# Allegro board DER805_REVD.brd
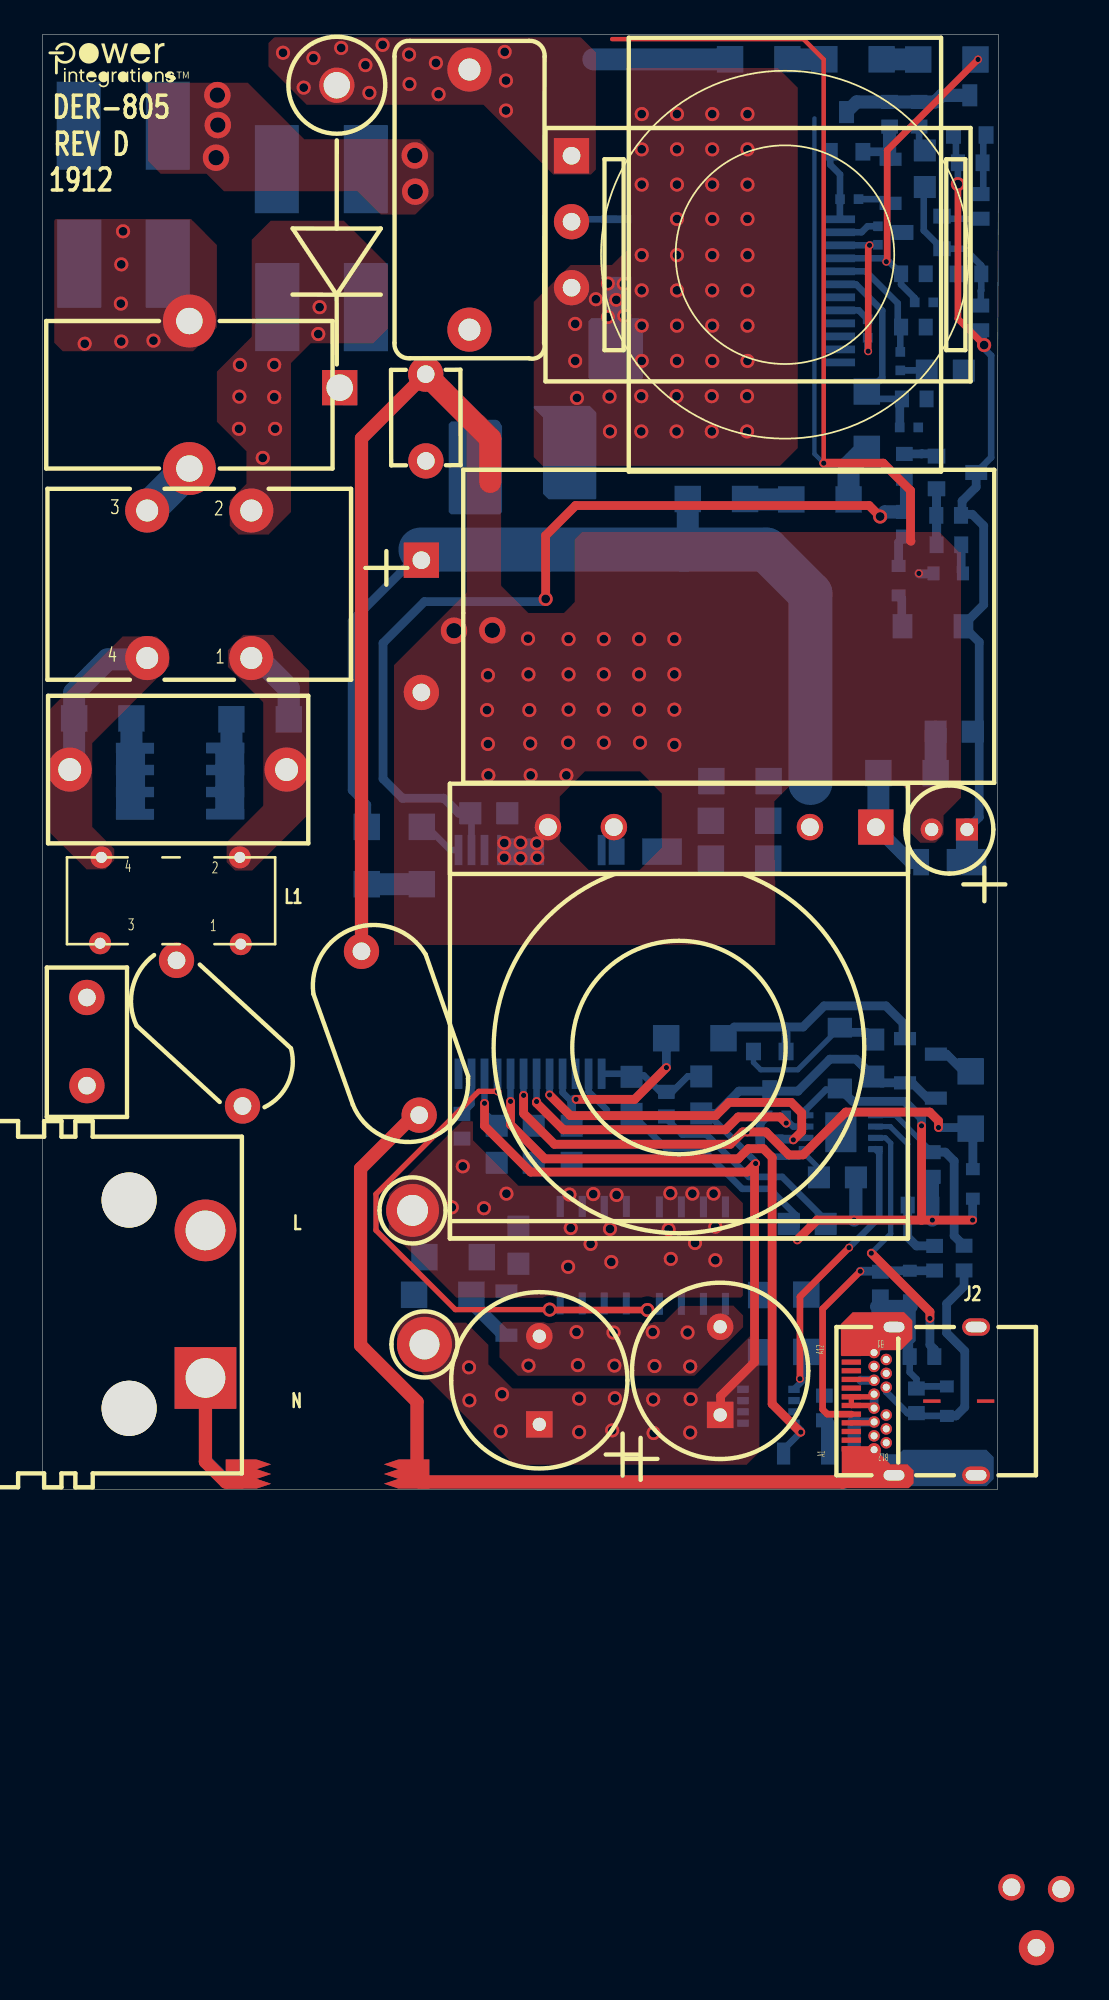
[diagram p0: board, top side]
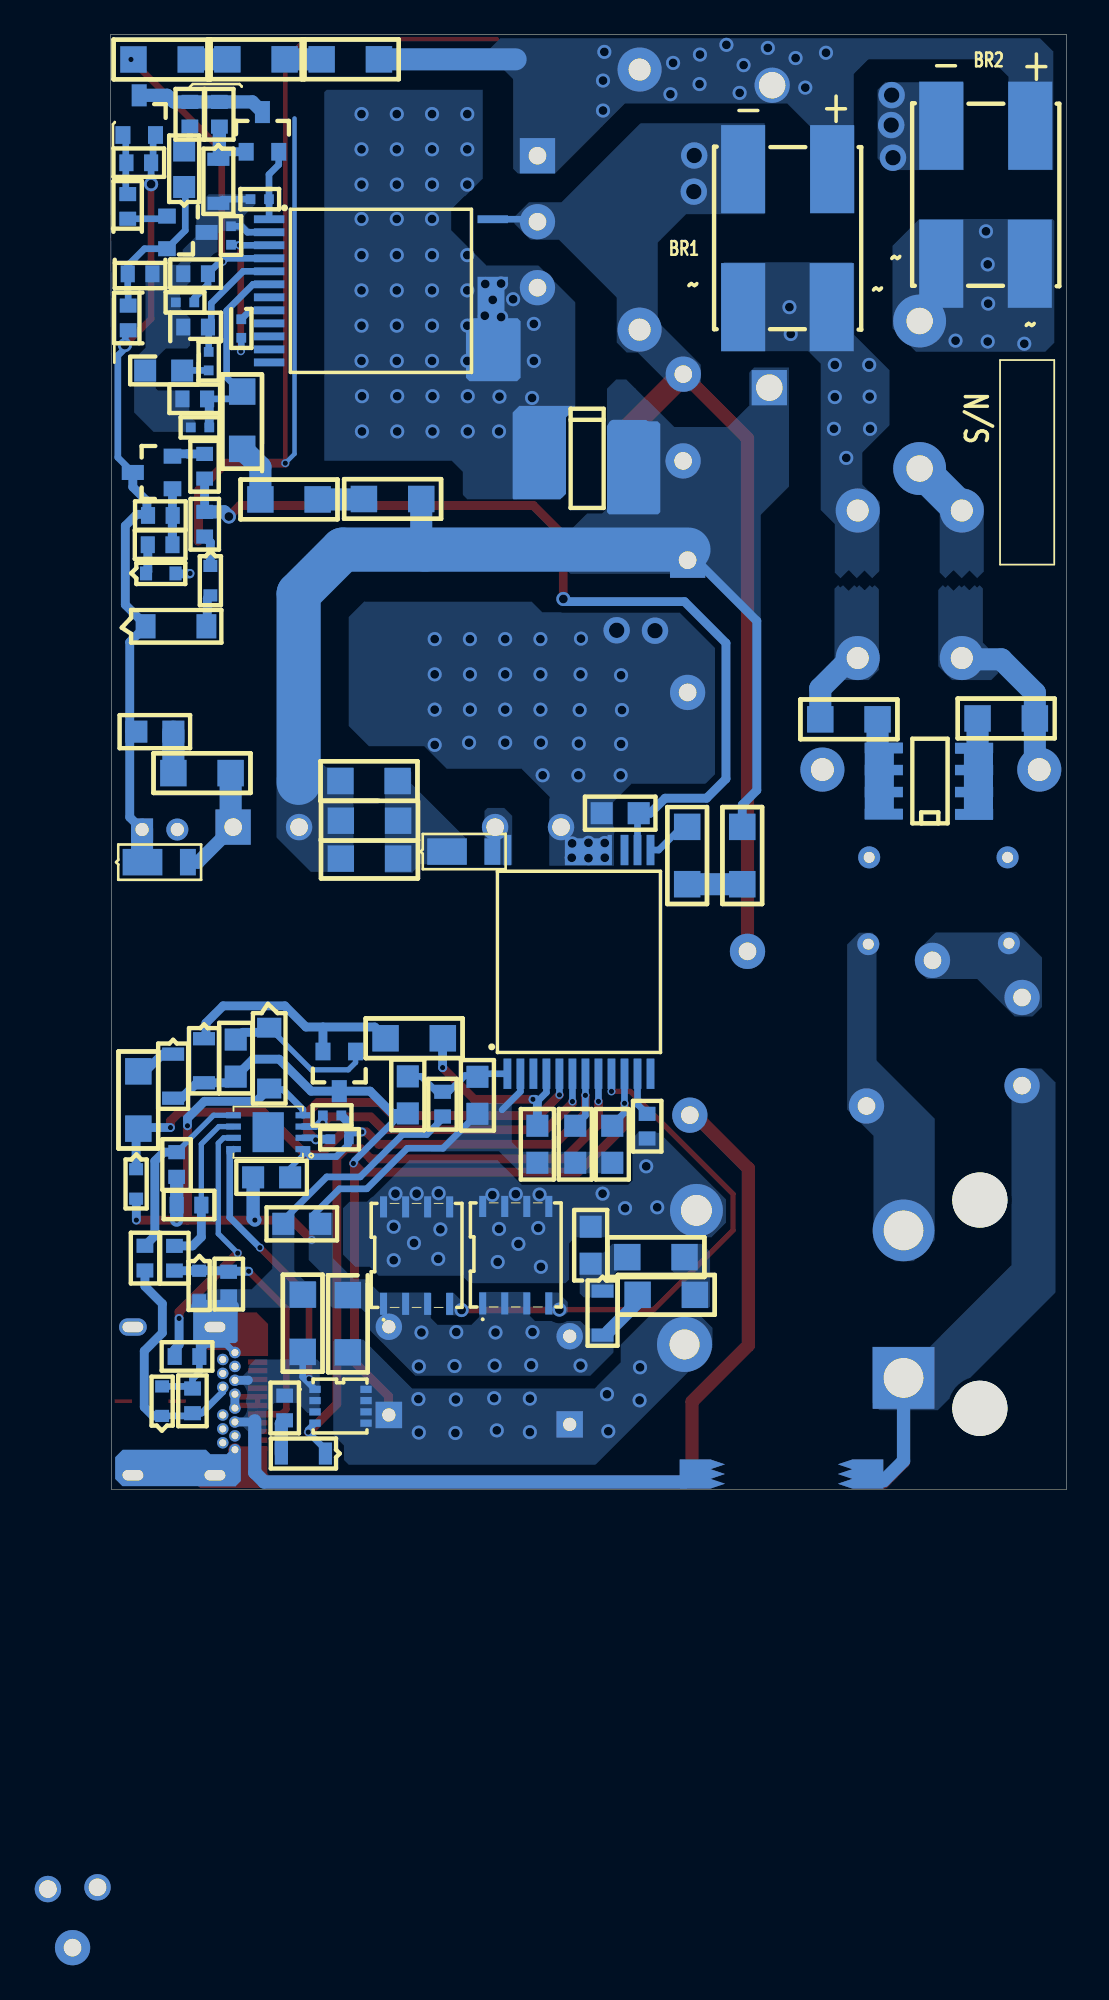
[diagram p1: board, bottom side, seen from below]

Outline 55.12 x 83.82 mm; copper layers: TOP, GND, VCC, BOTTOM. Coordinates in mm from the lower left corner of the outline.
Outline path: 0,83.82 0,0 55.04,0 55.04,55.02 55.12,83.82 0,83.82

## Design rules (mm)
constraint set DEFAULT: min track width 0.203

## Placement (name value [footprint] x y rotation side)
BR1  Z4DGP408L-HF  [PI_SM_D_Z4D]  13.54 76.12 180 bottom
BR2  Z4DGP408L-HF  [PI_SM_D_Z4D]  2.12 78.63 180 bottom
C1  330 nF  [PINP_XCAPRAD15X8P5X14HD040]  1.57 41.48 0 top
C2  82 uF  [PI_CAP_CLY_D710_LS300_040_1035H]  21.84 53.54 270 bottom
C3  470 pF  [PINPCAPRAD374X275LS394D030]  18.39 31.01 289.4 top
C4  2.2 nF  [PISMC1206]  41.83 36.35 180 bottom
C5  22 uF  [PIPOLCAPCLYD200LS80030]  53.29 38.02 180 top
C6  4.7 uF  [PISMC0805]  24.66 38.96 0 bottom
C9  2.2 uF  [PISMC0805]  30.51 18.82 90 bottom
C10  4.7 uF  [PISMC0805]  33.96 21.64 90 bottom
C11  2.2 uF  [PISMC0805]  28.32 18.82 90 bottom
C12  680 uF  [PIPOLCAPCLYD400LS200030]  28.64 3.75 90 top
C13  680 uF  [PIPOLCAPCLYD400LS200030]  39.07 4.29 90 top
C15  2.2 uF  [PISMC1206]  44.03 7.92 90 bottom
C16  270 pF  [PISMC0603]  50.38 5.82 270 bottom
C17  2.2 uF  [PISMC0805]  44.75 17.98 0 bottom
C18  2.2 uF  [PISMC0805]  26.19 18.82 90 bottom
C19  270 pF  [PISMC0603]  49.87 16.38 0 bottom
C20  270 pF  [PISMC0603]  51.3 19.43 270 bottom
C21  1.0 uF  [PI_NP_CAP_RAD717X335LS590D050]  24.61 81.81 270 top
C22  1 uF  [PISMR0402]  45.97 74.35 0 bottom
C23  100 nF  [PISMR0402]  48.16 71.72 90 bottom
C24  470 pF  [PISMC0603]  49.49 70.05 0 bottom
C25  150 nF  [PISMC0603]  49.49 66.98 0 bottom
C26  2.2 uF  [PISMC0805]  50.98 64.47 0 bottom
C27  0.022 uF  [PINPXCAPRAD5P5MMX4P0D040]  22.1 59.26 90.1 top
C28  470 pF  [PISMC0603]  49.54 62.84 0 bottom
C34  2.2 nF  [PISMC0805]  27.43 15.14 270 bottom
C35  NA  [PISMC0805]  53.62 43.66 180 bottom
C36  10 uF  [PISMC1206]  41.43 11.2 270 bottom
C37  270 pF  [PISMC0603]  48.3 11.12 90 bottom
D1  DFLR1800-7  [PISMDDFLR120012]  35.74 36.75 0 bottom
D2  DFLR1400-7  [PISMDDFLR120012]  53.29 36.14 0 bottom
D3  1N5407-E3/54  [PIDV300X200X060DO15D0201AD]  16.96 65.67 90 top
D4  LXA03D530  [PI_SM_DIODE_SO8C]  30.12 61.32 270 bottom
D5  1N4148WS  [PISMDSOD323]  50.86 75.04 90 bottom
D6  DZ2J240M0L  [PI_SM_D_SSMINI2P]  52.13 4.24 90 bottom
D7  BAV19WS  [PISMSOD323]  26.75 11.43 270 bottom
D8  DA2S10100L  [PISMDSOD52312]  49.35 53.21 270 bottom
D9  BAV21WS-7-F  [PISMSOD323]  42.72 2.07 0 bottom
D10  DZ2J240M0L  [PI_SM_D_SSMINI2P]  50 12.6 270 bottom
D11  BAV16WS-7-F  [PISMSOD323]  51.5 25.08 270 bottom
D12  BAV16WS-7-F  [PISMSOD323]  49.72 25.97 270 bottom
F1  3.15 A  [PI_RST_MICROFUSE]  2.57 23.27 90 top
FL1  Hole_70mils  [PI_HOLE_70MIL]  22 8.36 270 top
FL2  Hole_70mils  [PI_HOLE_70MIL]  21.31 16.08 270 top
J1  CON2  [PI_IEC320-C8]  9.4 6.43 90 top
J2  CON24_USB_C  [PI_CONN_USBC_WURTH]  48.64 5.09 90 top
L1  250 uH  [PI_TOROID_CMC4P_V_275UH]  8.92 31.42 180 top
L2  04291-T231  [PI_CMC_18MH_SUMIDA]  12.04 47.9 180 top
L3  150 uH  [PI2P16P5X8P5X8P5LSD60]  8.47 58.82 90 top
NOREF  -  []  84.81 -222.45 0 top
NOREF#2  -  []  -0.2 83.26 0 top
NOREF#3  -  []  0 0 90 top
NOREF#4  -  []  0 83.82 0 top
NOREF#5  -  []  -334.16 -235.43 0 top
Q1  MMBTA06LT1G  [PISMSOT23123_1]  51.54 59.54 90 bottom
Q2  AON6220  [PISMPQFN5X6B]  33.66 10.72 180 bottom
Q3  AON6220  [PISMPQFN5X6B]  39.37 10.69 180 bottom
Q4  MMBT4401LT1G  [PISMSOT23123_1]  45.41 77.08 180 bottom
Q5  TP0610K-T1-E3  [PISMSOT23123_1]  52.51 78.04 180 bottom
Q7  AON7520  [PISM8DFN_EP3P3X3P3]  41.85 4.79 270 bottom
Q9  MMBT4401LT1G  [PISMSOT23123_1]  42.86 25.23 0 bottom
R1  75 k  [PISMR1206]  1.83 44.42 0 bottom
R2  75 k  [PISMR1206]  10.9 44.37 0 bottom
R4  2.00 M  [PISMR1206]  18.69 34.87 90 bottom
R5  2.00 M  [PISMR1206]  21.87 38.18 270 bottom
R6  3 k  [PISMR1206]  53.51 24.09 270 bottom
R8  680 k  [PISMR1206]  41.83 38.53 180 bottom
R9  680 k  [PISMR1206]  41.86 40.82 180 bottom
R11  16.5 k  [PISMR0805]  47.89 23.79 90 bottom
R13  40.2  [PISMR1206]  39.26 26 180 bottom
R14  3 k  [PISMR0603]  49.68 59.66 270 bottom
R15  47  [PISMR0603]  49.68 54.9 90 bottom
R16  47  [PISMR0603]  24.18 20.22 90 bottom
R17  0.0  [PISMR0603]  51.54 54.43 0 bottom
R19  4.99  [PISMR1206]  22.02 13.39 0 bottom
R20  4.99  [PISMR1206]  21.42 11.21 0 bottom
R21  10  [PISMR0603]  35.97 22.91 270 bottom
R25  6.2 M  [PISMR1206]  42.94 82.4 180 bottom
R26  6.2 M  [PISMR1206]  48.37 82.4 180 bottom
R27  3.74 M  [PISMR1206]  50.48 82.39 0 bottom
R28  165.0 k  [PISMR0402]  50.28 68.4 0 bottom
R29  0.0  [PISMR0402]  47.57 67.42 270 bottom
R30  20 k  [PISMR0402]  49.45 65.54 270 bottom
R31  3.74 M  [PISMR1206]  37.2 57.07 0 bottom
R32  6.2 M  [PISMR1206]  43.17 57.04 0 bottom
R33  6.2 M  [PISMR1206]  47.52 63.26 270 bottom
R34  165.0 k  [PISMR0402]  50.48 61.19 180 bottom
R37  22  [PISMR0603]  51.42 14.03 270 bottom
R38  NA  [PISMR1206]  48.18 41.27 0 bottom
R40  100  [PISMR0603]  45.07 3.98 90 bottom
R41  4.70 k -DNP  [PISMR0402]  41.8 21.55 0 bottom
R42  4.70 k-DNP  [PISMR0402]  41.37 20.18 0 bottom
R43  22  [PISMR0603]  53.12 12.62 90 bottom
R44  422 k  [PISMR0805]  37.97 21.67 90 bottom
R45  0.006  [PISMR0805]  43.01 15.3 0 bottom
R46  200 k  [PISMR0603]  52.95 56.12 180 bottom
R47  215 k  [PISMR0603]  54.09 66.79 90 bottom
R48  24.9 k  [PISMR0603]  54.11 70.04 180 bottom
R49  7.5 k  [PISMR0603]  52.77 76.44 0 bottom
R50  30.1 k  [PISMR0603]  54.11 74.64 270 bottom
R51  100 k  [PISMR0603]  50.53 79.95 270 bottom
R52  200 k  [PISMR0603]  48.83 79.95 270 bottom
RT2  100 k  [PISMR0603]  49.99 7.66 0 bottom
RV1  275 Vac  [PIDISC500X225LS335X140040]  7.73 30.48 316.9 top
T1  PQ-2620  [PI_BOBBIN_PQ-2628_6P]  36.69 25.46 270 top
T2  EQ25  [PI_BOBBIN_EQ-2515P5_4P]  42.8 71.15 0 top
U1  INN3368C  [PI_IC_INSOP_24D]  32.23 23.95 90 bottom
U2  TL431CDBZR  [PISMSOT23123_1]  51.85 71.49 270 bottom
U3  CAP200DG  [PI_IC_SMD_SO8_CAPZERO]  5.33 38.91 90 bottom
U4  PFS7628C  [PI_IC_INSOP24B]  39.52 69.06 180 bottom
U5  VP302  [PI_SM_DFN-8]  44.02 19.61 90 bottom
VR1  MMSZ5258B-7-F  [PI_SM_SOD-123_12]  53.09 49.73 180 bottom
VR2  DZ2S100M0L  [PI_SM_D_SSMINI2P]  53.06 52.78 180 bottom
VR3  BZX384-B13,115  [PISMSOD323]  48.89 76.64 270 bottom
VR5  MMSZ5232B-7-F  [PI_SM_SOD-123_12]  45.96 26.61 270 bottom
VR6  DZ2S03900L  [PI_SM_D_SSMINI2P]  53.63 18.45 270 bottom

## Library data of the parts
BR1 BR2 = DISCRETE BRIDGE_+~~-
C1 = CAP NP: alternate symbols: (pinp_xcaprad15x8p5x14Hd040H)
C2 = CAP POL: alternate symbols: (pi_cap_cly_d710_ls300_040_1035h)
C3 C4 C6 C9-C11 C15-C20 C26 C34 C37 = CAP NP
C5 = CAP POL: alternate symbols: (pipolcapclyd5p0x12p5ls2p0d30h)
C12 C13 = CAP POL: alternate symbols: (pipolcapclyd400x530ls200030h)
C21 = CAP NP: room: 1
C22 C23 = CAP NP: alternate symbols: (pismr0402_1); room: 2
C24 C25 C27 C28 = CAP NP: room: 2
C35 = CAP NP: alternate symbols: (pismc0805_1)
C36 = CAP NP: alternate symbols: (pismc1206_1)
D1 D2 D5 D7 D9 D11 D12 = DIODE
D3 = DIODE: alternate symbols: (pidax800x225060do15do201ad,pidv300x200x060do14wbead,pidv600x200x060do14); room: 2
D4 = DIODE_A1K8
D6 D10 VR1 VR2 VR5 VR6 = DIODE_ZENER
D8 = DIODE: room: 1
F1 = FUSE: alternate symbols: (pirstmicrofusehoz)
FL1 FL2 = FlyingLead
J1 = CON2_ACIN
J2 = CON24_USB
L1 = TORRID 4P_12_34: alternate symbols: (pi_toroid_CMC4p_V,pi_toroid_CMC4p_V_275uH)
L2 = TORRID 4P_12_43a
L3 = INDUCTOR
Q1 Q9 = NPN_BEC
Q2 Q3 Q7 = FET_N_SGD_123_4_5678
Q4 = NPN_BEC: room: 2
Q5 = FET_P_GSD_1
R1 R2 R4-R6 R8 R9 R11 R13 R14 R17 R19-R21 R37 R38 R40-R52 = R
R15 R25-R34 = R: room: 2
R16 = R: alternate symbols: (pismr0603_1)
RT2 = THERMISTOR
RV1 = VARISTOR: alternate symbols: (pirad550x410ls300040_h)
T1 = BPQ26/28_6P
T2 = BEQ2506_4P
U1 = DEV_InnoPro
U2 = TL431CDBZR
U3 = CAPZero
U4 = DEV_HiperPFS7_inSOP
U5 = VP302: room: 3
VR3 = DIODE_ZENER: room: 2

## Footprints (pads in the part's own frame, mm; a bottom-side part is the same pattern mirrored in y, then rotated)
PI2P16P5X8P5X8P5LSD60
  round 3.048 hole 1.524: 1(0,0) 2(8.5,0)
PI_BOBBIN_EQ-2515P5_4P
  rect 2.032x2.032 hole 1.016: 1(-12.3,5.7)
  round 2.032 hole 1.016: 2(-12.3,1.9) 3(-12.3,-1.9) 4(14.497,-97.546)
PI_BOBBIN_PQ-2628_6P
  rect 2.032x2.032 hole 1.016: 1(-12.7,11.35)
  round 1.524 hole 1.016: 2(-12.7,7.55) 3(48.387,19.168) 4(-12.7,-3.75) 5(-12.7,-7.55) 6(48.489,22.026)
PI_CAP_CLY_D710_LS300_040_1035H
  rect 2.032x2.032 hole 1.016: 1(0,0)
  round 2.032 hole 1.016: 2(7.62,0)
PI_CMC_18MH_SUMIDA
  round 2.54 hole 1.27: 1(0,0) 2(0,-8.5) 3(6,-8.5) 4(6,0)
PI_CONN_USBC_WURTH
  oval 1x1.6 hole 0.6x1.2: (-4.27,-0.45) (-4.27,-5.18) (4.27,-0.45) (4.27,-5.18)
  round 0.66 hole 0.406: (-2,0.7) (2,0.7) B1(2.8,0.7) B2(2.4,0) B3(1.6,0) B4(1.2,0.7) B5(0.8,0) B6(0.4,0.7) B7(-0.4,0.7) B8(-0.8,0) B9(-1.2,0.7) B10(-1.6,0) B11(-2.4,0) B12(-2.8,0.7)
  rect 0.305x1.118 smd: A1(-2.75,2.01) A2(-2.25,2.01) A3(-1.75,2.01) A4(-1.25,2.01) A5(-0.75,2.01) A6(-0.25,2.01) A7(0.25,2.01) A8(0.75,2.01) A9(1.25,2.01) A10(1.75,2.01) A11(2.25,2.01) A12(2.75,2.01)
PI_HOLE_70MIL
  round 3.048 hole 1.778: 1(0,0.025)
PI_IC_INSOP24B
  rect 1.75x0.45 smd: 1(-6.445,4.125) 2(-6.445,3.375) 3(-6.445,2.625) 4(-6.445,1.875) 5(-6.445,1.125) 6(-6.445,0.375) 7(-6.445,-0.375) 8(-6.445,-1.125) 9(-6.445,-1.875) 10(-6.445,-2.625) 11(-6.445,-3.375) 12(-6.445,-4.125) 13(6.445,-4.125) 14(6.445,-3.375) 15(6.445,-2.625) 24(6.445,4.125)
  custom 0.438x0.438 smd: 16(6.445,-0.545)
PI_IC_INSOP_24D
  rect 1.75x0.45 smd: 1(0,0) 2(0,-0.75) 3(0,-1.5) 4(0,-2.25) 5(0,-3) 6(0,-3.75) 7(0,-4.5) 8(0,-5.25) 9(0,-6) 10(0,-6.75) 11(0,-7.5) 12(0,-8.25) 13(12.89,-8.25) 14(12.89,-7.5) 15(12.89,-6.75) 24(12.89,0)
  custom 0.438x0.438 smd: 16(12.89,-4.67)
PI_IC_SMD_SO8_CAPZERO
  rect 0.599x2.2 smd: 1(0,0) 2(1.27,0) 3(2.54,0) 4(3.81,0) 5(3.81,5.199) 6(2.54,5.199) 7(1.27,5.199) 8(0,5.199)
PI_IEC320-C8
  round 3.175 hole 3.175 unplated: (-1.75,4.4) (10.25,4.4)
  rect 3.556x3.556 hole 2.286: 1(0,0)
  round 3.556 hole 2.286: 2(8.5,0)
PI_NP_CAP_RAD717X335LS590D050
  round 2.54 hole 1.27: 1(0,0) 2(14.986,0)
PI_RST_MICROFUSE
  round 2.032 hole 1.016: 1(0,0) 2(5.08,0)
PI_SM_D_SSMINI2P
  rect 0.699x0.8 smd: 1(0,0) 2(1.7,0)
PI_SM_D_Z4D
  rect 2.54x5.08 smd: 1(0.025,-0.051) 2(0,-8.001) 3(-5.105,-8.001) 4(-5.105,-0.051)
PI_SM_DFN-8
  rect 0.35x0.85 smd: 1(0,0) 2(0.65,0) 3(1.3,0) 4(1.95,0) 5(1.95,4) 6(1.3,4) 7(0.65,4) 8(0,4)
  rect 2.3x1.8 smd: 9(0.975,2)
PI_SM_DIODE_SO8C
  oval 0.635x2.388 smd: (1.27,0) (1.27,4.902) (2.54,4.902) (3.81,0) (3.81,4.902) 8(0,4.902)
  rect 0.635x2.388 smd: 1(0,0)
PI_SM_SOD-123_12
  rect 1.143x1.397 smd: 1(0,0) 2(3.505,0)
PI_TOROID_CMC4P_V_275UH
  round 1.27 hole 0.635: 1(-2.515,0) 2(-2.464,-5) 3(5.591,-0.051) 4(5.515,-5)
PIDISC500X225LS335X140040
  round 2.032 hole 1.016: 1(0,0) 2(8.509,-3.531)
PIDV300X200X060DO15D0201AD
  rect 2.032x2.032 hole 1.524: 1(-2.184,-0.18)
  round 2.032 hole 1.524: 2(15.24,0)
PINP_XCAPRAD15X8P5X14HD040
  round 2.54 hole 1.321: 1(0,0) 2(12.5,0)
PINPCAPRAD374X275LS394D030
  round 2.032 hole 1.016: 1(0,0) 2(10.008,0)
PINPXCAPRAD5P5MMX4P0D040
  round 2.032 hole 1.016: 1(0,0) 2(5,0)
PIPOLCAPCLYD200LS80030
  rect 1.27x1.27 hole 0.762: 1(0,0)
  round 1.27 hole 0.762: 2(2.032,0)
PIPOLCAPCLYD400LS200030
  rect 1.524x1.524 hole 0.762: 1(0,0)
  round 1.524 hole 0.762: 2(5.08,0)
PISM8DFN_EP3P3X3P3
  rect 0.42x0.66 smd: 1(-0.975,-1.47) 2(-0.325,-1.47) 3(0.325,-1.47) 4(0.975,-1.47) 5(0.975,1.47) 6(0.325,1.47) 7(-0.325,1.47) 8(-0.975,1.47)
PISMC0603
  rect 0.813x0.965 smd: 1(0,0) 2(1.422,0)
PISMC0805
  rect 1.27x1.27 smd: 1(0,0) 2(2.134,0)
PISMC1206
  rect 1.524x1.524 smd: 1(0,0) 2(3.302,0)
PISMDDFLR120012
  rect 2.286x1.524 smd: 1(-0.025,0)
  rect 0.914x1.524 smd: 2(-2.642,0)
PISMDSOD323
  rect 1.27x1.27 smd: 1(0,0) 2(2.108,0)
PISMDSOD52312
  rect 0.699x0.8 smd: 1(0,0) 2(1.7,0)
PISMPQFN5X6B
  rect 0.406x1.27 smd: 1(0,0) 2(1.27,0) 3(2.54,0) 4(3.81,0)
  rect 0.406x1.219 smd: 5(3.81,5.588) 6(2.54,5.588) 7(1.27,5.588) 8(0,5.588)
PISMR0402
  rect 0.559x0.559 smd: 1(0,0) 2(1.067,0)
PISMR0603
  rect 0.813x0.965 smd: 1(0,0) 2(1.422,0)
PISMR0805
  rect 1.27x1.27 smd: 1(0,0) 2(2.134,0)
PISMR1206
  rect 1.524x1.524 smd: 1(0,0) 2(3.302,0)
PISMSOD323
  rect 0.762x1.27 smd: 1(0,0) 2(2.54,0)
PISMSOT23123_1
  rect 0.864x1.016 smd: 1(-1.88,0) 2(0,0)
  rect 0.864x1.27 smd: 3(-0.94,2.286)

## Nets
GND: C3.2 C15.2 C16.1 C37.1 D6.2 D10.2 J2.A1 J2.A12 J2.B1 J2.B12 R21.2 R45.2 RT2.1
GND_SIGNAL: C9.1 C10.1 C11.1 C12.2 C13.2 C17.2 C18.1 C19.2 C20.2 C36.1 D7.2 Q2.1 Q2.2 Q2.3(S3) Q3.1 Q3.2 Q3.3(S3) R20.2 R45.1 U1.2 U5.4 VR5.2 VR6.2
VBUS_OUT: C15.1 J2.A4 J2.A9 J2.B4 J2.B9(VBUS4) Q7.1 Q7.2 Q7.3(S3) R40.2 U5.8
VCCP: C5.1 C35.1 D2.1 Q1.3 Q5.2(S) R46.1 R47.1 R49.1 VR1.1
B+: C2.1 C4.1 C27.1 D3.1 D4.8(K) R4.2 R8.1 R9.1 R31.1 T1.2
BPS: C9.2 R13.2 U1.4
NC3: U1.3
NC9: U4.9
NC10: U4.10
NC11: U4.11
NC12: U4.12
NC13: U4.13
NC14: U4.14
NC15: U4.15
RTN: BR1.4 BR2.4 C2.2 C3.1 C5.2 C6.2 C21.2 C27.2 T1.5 T2.2 U1.16 U4.24 VR2.2
SCL: R42.2 U1.5 U5.2
SDA: R41.2 U1.6 U5.3
UVCC: C11.2 C17.1 R6.2 R41.1 R42.1 U1.7 U5.1(VCC) VR6.1
VOUT: C12.1 C13.1 C18.2 C36.2 D11.2 D12.2 FL1.1 Q7.5 Q7.6 Q7.7 Q7.8 Q9.3 R11.1 R44.1 U1.10(VOUT)
VRECT: BR1.1 BR2.1 C21.1 D3.2 R25.2 T2.1
N11472557: R4.1 R5.2
N11472561: C4.2 D1.1 R8.2 R9.2
N11472857: R5.1 U1.13
N11473069: C34.2 D7.1 R19.2
N11473107: D1.2 T1.4 U1.24
N11473227: C34.1 FL2.1 Q2.5 Q2.6 Q2.7 Q2.8 Q3.5 Q3.6 Q3.7 Q3.8 R16.1
N11473427: Q2.4 Q3.4 U1.9
N11473461: D2.2 R38.1 T1.1
N11473829: L2.3 L3.1
N11473833: R16.2 U1.11
N11473875: Q1.1 R17.1 R46.2
N11473955: BR1.2 BR1.3(AC2) L2.2
N11473967: Q1.2(EMITTER) R14.1
N11474105: C6.1 R14.2 R15.2 U1.14
N11474149: C1.1 L1.4 L2.4 R1.1
N11474157: C1.2 L1.2 L2.1 R2.2
N11474629: D4.1 T2.3 U4.16
N11474695: R31.2 R32.1
N11474767: R25.1 R26.2
N11474787: C22.1 Q4.2(EMITTER) U4.1(VCC)
N11474815: C28.1 R33.1 R34.2 U4.6
N11474857: R26.1 R27.1
N11474861: C25.1 R30.1 U4.5
N11474877: R32.2 R33.2
N11474897: R29.1 U4.8
N11474981: C24.1 R27.2 R28.1 U4.4
N11474993: C22.2 C23.2 C24.2 C25.2 C26.2 C28.2 R28.2 R34.1 R48.2 U2.3 U4.2 VR3.2
N11474997: C23.1 R29.2 U4.3
N11475055: Q4.3 Q5.3 R51.1 R52.1
N11475093: C26.1 R30.2
N11475097: F1.2 L1.3 RV1.1
N11475353: F1.1 J1.1
N11475357: J1.2 L1.1 RV1.2
N11530054: Q4.1 R52.2 VR3.1
N11567485: R1.2 U3.2
N11567493: R2.1 U3.7
N11571354: D8.1 R15.1
N11571367: D8.2 VR1.2
N11586649: BR2.2 BR2.3(AC2) L3.2
N11591526: C35.2 R38.2
N12158428: D9.1 Q7.4 U1.8
N12158455: D9.2 R40.1
N12185398: C16.2 D6.1 J2.B5 R43.1
N12185402: C37.2 D10.1 J2.A5 R37.2
N12185406: RT2.2 U5.7
N12185524: C19.1 R37.1 U5.6
N12185556: J2.A6 J2.A7 J2.B6 J2.B7
N12185614: C20.1 R43.2 U5.5
N12197697: C10.2 R21.1 R44.2 U1.1
N12203170: R17.2 VR2.1
N12231621: D5.1 R47.2 R48.1 U2.2(VREF)
N12232589: Q5.1 R49.2 R50.1
N12263719: D12.1 Q9.2(EMITTER) R13.1
N12263747: Q9.1 R11.2 VR5.1
N12265542: R19.1 R20.1
N12279931: D11.1 R6.1
N122316481: R50.2 U2.1
N122329820: D5.2 R51.2

Pads without a net: J2 A2 A3 A8 A10 A11 B2 B3 B8 B10 B11; T1 3 6; T2 4; U1 12 15; U3 1 3 4 5 6 8; U4 7; U5 9

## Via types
v1: diameter 0.457, hole 0.305, TOP to BOTTOM, 30 vias
v2: diameter 0.813, hole 0.508, TOP to BOTTOM, 158 vias
v3: diameter 1.524, hole 0.889, TOP to BOTTOM, 7 vias

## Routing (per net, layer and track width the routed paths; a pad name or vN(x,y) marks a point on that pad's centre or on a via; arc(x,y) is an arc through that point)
GND: length 77.5
  TOP w0.254: J2.A1 46.68,2.29 J2.B12 ; 46.55,7.84 J2.A12 47.89,7.84 J2.B1
  TOP w0.762: 21.59,0.81 21.59,5.05 18.34,8.31 18.34,18.49 21.41,21.57 C3.2 ; 21.74,0.43 46.13,0.43 47.94,2.24 J2.B12
  BOTTOM w0.381: RT2.1 49.99,6.76 50.38,6.36 C16.1 50.5,5.94 D6.2 ; RT2.1 49.99,7.98 49.61,8.36 48.44,8.36 47.97,7.89 J2.B1 ; RT2.1 50,7.67 D10.2 ; R45.2 45.15,15.51 42.65,18.01 40.72,18.01 38.28,20.45 36.88,20.45 35.97,21.36 R21.2 ; 44.14,11.12 C15.2
  BOTTOM w0.762: 50.08,10.54 48.08,10.54
  BOTTOM w1.27: C3.2 21.72,21.32 21.69,21.3
GND_SIGNAL: length 50.2
  TOP w0.508: v1(43.51,14.38) 44.65,15.52 v1(46.79,15.52) 50.67,15.52 ; 50.67,15.52 v1(50.67,20.95) ; 50.67,15.52 v1(51.3,15.52) v1(53.62,15.52)
  BOTTOM w0.381: 43.46,15.11 43.46,15.77 41.91,17.32 40.34,17.32 38,19.66 35.94,19.66 C10.1 33.58,22.02 ; U1.2 31.48,22.92 32.54,21.87 ; C36.1 40.89,11.2 ; U5.4 44.02,21.89 45.16,23.04 45.9,23.04 VR5.2 ; 28.94,8.83 C12.2
  BOTTOM w0.508: VR5.2 46.7,22.36 49.7,22.36 50.67,21.39 v1(50.67,20.95) ; v1(53.62,15.52) 53.62,16.49 53.63,16.5 VR6.2
  BOTTOM w0.762: 26.42,9.09 24.73,10.78 R20.2 ; C20.2 C19.2 v1(51.3,15.52) ; C17.2 46.89,15.62 v1(46.79,15.52)
  vias: v2(28.02,7.14) v2(30.78,9.07) v2(30.86,7.16) v2(32.92,9.04) v2(32.97,7.14) v2(35.18,9.07) v2(35.28,7.11) v2(37.19,9.04) v2(37.34,7.09)
VBUS_OUT: length 50.3
  TOP w0.254: J2.B4 47.89,6.34 J2.A9
  TOP w0.305: J2.A4 47.89,3.84 J2.B9
  TOP w0.381: v1(46.49,13.93) 43.66,11.1 v1(43.66,6.38)
  BOTTOM w0.381: U5.8 48.23,19.39 48.23,15.67 v1(46.49,13.93) ; Q7.1 44.03,6.48 C15.1
  BOTTOM w0.508: 47.17,6.3 47.18,6.29 J2.B4 ; J2.B9 46.86,3.89 46.79,3.96
  BOTTOM w0.762: 21.97,0.43 46.25,0.43 46.79,0.97 46.79,3.96
VCCP: length 47.1
  TOP w0.381: v2(54.28,65.94) 52.77,67.45 v2(52.77,75.21)
  BOTTOM w0.381: 54.25,65.76 54.25,66.62 R47.1 ; 54.25,65.76 54.28,65.79 v2(54.28,65.94) ; 54.25,65.76 54.69,65.33 54.69,59.46 Q1.3 ; Q5.2 52.65,77.9 52.65,76.56 R49.1 v2(52.77,75.21)
  BOTTOM w0.508: C5.1 54,38.73 54,43.69 ; C35.1 53.98,43.66 54,43.69 ; 54,43.69 54,48.82 VR1.1 53.09,49.81 54.25,50.98 54.25,55.52 53.59,56.18 53.01,56.18 ; 53.01,56.18 R46.1 ; 53.01,56.18 53.01,56.95 53.82,57.76 Q1.3
  BOTTOM w1.27: D2.1 53.29,36.17 C5.1
B+: length 55.6
  BOTTOM w0.508: R4.2 18.69,39.45 17.86,40.28 17.86,50.05 21.77,53.96 21.77,53.62 21.79,53.59
  BOTTOM w1.27: 36.98,54.15 37.2,54.37 R31.1
  BOTTOM w2.54: 44.27,40.71 44.27,51.61 41.73,54.15 21.79,54.15
BPS: length 11.2
  TOP w0.508: v1(35.97,24.31) 34.14,22.48 v1(30.76,22.48)
  BOTTOM w0.381: 30.51,22.35 29.98,22.87 U1.4
  BOTTOM w0.508: v1(30.76,22.48) 30.63,22.48 30.51,22.35 C9.2 ; R13.2 35.97,25.98 v1(35.97,24.31) 35.95,24.32
RTN: length 111.1
  TOP w0.254: 32.84,83.57 43.87,83.57 45.03,82.4 v1(45.03,59.13) 44.98,59.08
  TOP w0.508: 50.06,54.64 50.04,54.66 50.04,57.56 48.46,59.13 v1(45.03,59.13)
  TOP w0.762: C27.2 18.39,60.56 C3.1
  TOP w1.27: C27.2 25.81,60.54 25.81,58.05 ; 25.99,49.45 v3(25.93,49.5)
  BOTTOM w0.254: v1(45.03,59.13) 44.5,59.66 44.5,78.99
  BOTTOM w0.381: U4.24 31.07,73.19 30.81,73.45
  BOTTOM w0.508: VR2.2 51.34,52.76 50.55,52.76 v1(50.52,52.78)
  BOTTOM w0.762: U1.16 27.39,36.67 27.39,36.38
  vias: v2(25.63,44.91) v2(25.68,46.91) v2(25.68,42.95) v2(25.7,41.15) v2(26.62,37.25) v2(26.62,36.4) v2(27.56,37.26) v2(27.56,36.37) v2(27.99,49.02) v2(28.02,46.96) v2(28.07,44.91) v2(28.12,42.98) v2(28.14,41.15) v2(28.5,37.22) v2(28.52,36.4) v2(30.2,41.15) v2(30.33,49) v2(30.33,46.96) v2(30.33,44.93) v2(30.3,43.03) v2(32.36,49) v2(32.36,46.96) v2(32.36,44.93) v2(32.36,43.03) v2(34.39,49) v2(34.39,46.96) v2(34.39,44.93) v2(34.44,43.03) v2(36.42,49) v2(36.42,46.96) v2(36.42,44.93) v2(36.42,42.9) v3(10.01,76.73) v3(10.08,80.34) v3(10.11,78.61) v3(21.46,76.86) v3(21.49,74.78) v3(23.72,49.48)
SCL: length 20.2
  TOP w0.508: v1(43.28,20.14) 43.76,20.62 43.76,21.69 43.15,22.3 39.57,22.3 38.81,21.54 30.43,21.54 v1(29.23,22.73)
  BOTTOM w0.381: U1.5 v1(29.23,22.73) ; v1(43.28,20.14) 43.4,20.26 U5.2
  BOTTOM w0.508: R42.2 43.24,20.18 v1(43.28,20.14)
SDA: length 19.1
  TOP w0.508: v1(28.48,22.35) 28.48,22.27 30.02,20.73 39.37,20.73 40.11,21.46 42.52,21.46 v1(42.88,21.11)
  BOTTOM w0.381: 42.88,21.32 43.28,20.91 U5.3 ; U1.6 v1(28.48,22.35)
  BOTTOM w0.508: R41.2 42.87,21.11 v1(42.88,21.11) 42.88,21.32
UVCC: length 43.3
  TOP w0.508: v1(27.74,22.71) 27.74,21.67 29.51,19.89 39.65,19.89 40.36,20.6 v1(40.61,20.6) 41.71,20.6 43.03,19.28 43.84,19.28 46.3,21.74 51.14,21.74 51.65,21.23 v1(51.65,20.85)
  BOTTOM w0.305: C17.1 44.73,18.01 44.73,18.54 44.02,19.25 U5.1
  BOTTOM w0.381: U1.7 27.73,22.71 v1(27.74,22.71) 27.74,21.54 C11.2 ; U5.1 43.59,19.18 42.09,19.18 41.37,19.89 R42.1
  BOTTOM w0.508: v1(40.61,20.6) 41.35,20.6 41.37,20.62 ; R41.1 41.37,21.12 41.37,20.62 ; 41.37,20.62 R42.1 ; v1(51.65,20.85) 53.44,20.85 R6.2 53.63,20.66 VR6.1
VOUT: length 57.3
  TOP w0.508: 41.05,18.72 40.61,18.29 28.14,18.29 25.48,20.95 v1(25.48,22.25) ; 41.05,18.72 v1(41.11,18.78) ; 41.05,18.72 41.05,7.34 39.09,5.38 39.09,4.32 C13.1
  BOTTOM w0.381: U1.10 v1(25.48,22.25) 25.48,21.71 26.19,21.01 C18.2 ; C13.1 38.52,3.75 ; v1(41.11,18.78) 41.05,18.85 41.05,18.95 38.33,21.67
  BOTTOM w0.508: R44.1 38.86,21.67 40.14,22.95 Q9.3 43.55,22.95 45.39,24.79 46.89,24.79 R11.1 47.97,23.79 48.32,23.43 D12.2 50.13,23.43 51.02,22.54 D11.2
  vias: v2(24.59,7.04) v2(24.61,5.13) v2(26.42,3.35) v2(26.49,5.49) v2(30.94,5.23) v2(30.94,3.3) v2(32.84,3.4) v2(32.99,5.26) v2(35.2,5.18) v2(35.23,3.25) v2(37.34,3.28) v2(37.36,5.21)
VRECT: length 7.9
  BOTTOM w1.27: 31.76,82.4 R25.2
  vias: v2(13.87,82.78) v2(15.06,80.77) v2(15.62,82.47) v2(17.22,83.06) v2(18.62,82.07) v2(18.85,80.47) v2(19.61,83.24) v2(21.13,82.68) v2(21.16,80.98) v2(22.68,82.19) v2(22.83,80.39) v2(26.64,82.83) v2(26.72,81.18) v2(26.72,79.45)
N11472557: length 3.2
  BOTTOM w1.27: R5.2 R4.1
N11472857: length 2.7
  BOTTOM w0.381: U1.13 23.51,36.84 22.17,38.18 R5.1
N11473227:
  vias: v2(23.6,16.26) v2(24.23,18.62) v2(25.45,16.21) v2(26.75,17.04) v2(30.3,12.83) v2(30.38,16.99) v2(30.45,15.06) v2(31.6,14.15) v2(31.75,17.02) v2(32.72,15.01) v2(32.79,13.11) v2(33.1,16.97) v2(36.09,14.99) v2(36.2,17.07) v2(36.22,13.28) v2(37.47,17.04) v2(37.62,14.2) v2(38.68,17.04) v2(38.79,15.14) v2(38.79,13.21)
N11473427: length 30.1
  TOP w0.305: v2(29.24,10.36) 23.8,10.36 19.23,14.94 19.23,17.02 25.15,22.94 v1(26.23,22.94)
  TOP w0.381: v2(29.24,10.36) 29.26,10.34 v2(34.87,10.34)
  BOTTOM w0.305: U1.9 v1(26.23,22.94)
N11473461: length 6.6
  BOTTOM w0.762: T1.1 50.06,36.14 D2.2
  BOTTOM w1.27: T1.1 48.18,38.31 R38.1
N11473829: length 3.9
  BOTTOM w1.27: 6.04,56.85 L2.3
  BOTTOM w2.032: L2.3 8.46,58.82 L3.1
N11473833: length 2.5
  BOTTOM w0.381: U1.11 24.73,22.19 R16.2
N11473875: length 4.9
  BOTTOM w0.508: Q1.1 R17.1 51.55,54.44 51.55,56.1 R46.2
N11473955:
  vias: v2(11.33,61.11) v2(11.38,64.8) v2(11.35,62.97) v2(12.7,59.44) v2(13.36,64.8) v2(13.36,62.94) v2(13.41,61.11) v2(15.9,66.57) v2(15.98,68.12)
N11473967: length 1.9
  BOTTOM w0.508: Q1.2 51.4,59.67 50.68,59.67 50.67,59.66 R14.1
N11474105: length 53.6
  TOP w0.508: v2(48.29,56.06) 47.65,56.69 30.73,56.69 29.01,54.97 v2(29.01,51.31)
  BOTTOM w0.381: U1.14 24.73,38.89 C6.1
  BOTTOM w0.508: R15.2 49.68,56.33 R14.2 ; C6.1 24,38.96 23.14,39.83 20.75,39.83 19.63,40.94 19.63,48.77 22.02,51.16 28.85,51.16 v2(29.01,51.31)
  BOTTOM w0.762: R15.2 48.55,56.32 v2(48.29,56.06)
N11474149: length 9.6
  BOTTOM w1.27: C1.1 1.83,41.73 R1.1 1.83,45.9 3.76,47.83 5.96,47.83 L2.4
N11474157: length 4.7
  BOTTOM w1.27: R2.2 14.2,46.15 12.45,47.9 L2.1
N11474629:
  vias: v2(30.71,67.16) v2(30.71,65.02) v2(30.81,62.89) v2(31.9,68.58) v2(32.59,69.48) v2(32.59,67.55) v2(32.69,62.97) v2(32.72,60.96) v2(33.08,68.54) v2(33.51,69.46) v2(33.53,67.63) v2(34.54,79.25) v2(34.54,77.22) v2(34.54,75.18) v2(34.54,71.12) v2(34.54,69.09) v2(34.54,67.06) v2(34.54,65.02) v2(34.52,62.99) v2(34.52,60.96) v2(36.58,79.25) v2(36.58,77.22) v2(36.58,75.18) v2(36.58,73.2) v2(36.58,71.12) v2(36.58,69.09) v2(36.58,67.06) v2(36.58,65.02) v2(36.55,62.99) v2(36.55,60.96) v2(38.61,79.25) v2(38.61,77.22) v2(38.61,75.18) v2(38.61,73.2) v2(38.61,71.12) v2(38.61,69.09) v2(38.61,67.06) v2(38.61,65.02) v2(38.58,62.99) v2(38.58,60.96) v2(40.64,79.25) v2(40.64,77.22) v2(40.64,75.18) v2(40.64,73.2) v2(40.64,71.12) v2(40.64,69.09) v2(40.64,67.06) v2(40.64,65.02) v2(40.61,62.99) v2(40.61,60.96)
N11474695: length 2.7
  BOTTOM w1.27: R31.2 40.53,57.04 R32.1
N11474767: length 2.1
  BOTTOM w1.27: R26.2 R25.1
N11474787: length 4.1
  BOTTOM w0.381: Q4.2 45.41,76.33 45.97,75.77 C22.1 45.97,74.09 45.97,74.09 U4.1
N11474815: length 12
  BOTTOM w0.381: C28.1 48.03,62.84 47.6,63.26 ; 47.6,63.26 R33.1 ; 47.6,63.26 48.41,64.07 48.41,67.92 46.89,69.44 U4.6
  BOTTOM w0.508: C28.1 49.42,62.71 R34.2
N11474857: length 2.1
  BOTTOM w1.27: R27.1 50.47,82.4 R26.1
N11474861: length 7
  BOTTOM w0.381: R30.1 49.45,66.93 C25.1 49.3,67.17 49.3,68.35 47.46,70.19 U4.5
N11474877: length 3.3
  BOTTOM w1.27: R33.2 46.47,58.91 R32.2
N11474897: length 1.8
  BOTTOM w0.381: R29.1 47.06,67.94 U4.8
N11474981: length 19.7
  TOP w0.381: v1(48.64,70.74) 48.69,70.79 48.69,77.16 v1(53.93,82.39)
  BOTTOM w0.381: U4.4 48.44,70.94 v1(48.64,70.74) 48.8,70.74 C24.1 49.49,69.43 50.28,68.64 R28.1
N11474993: length 4.3
  BOTTOM w0.381: U4.2 47.22,72.44 47.56,72.78 C23.2 ; 51.31,68.44 R28.2 ; C22.2 48.65,74.35 VR3.2
N11474997: length 9.1
  TOP w0.381: v1(47.68,71.69) 47.6,71.61 47.6,66.18 47.6,66.18 v1(47.6,65.58)
  BOTTOM w0.381: R29.2 47.57,65.61 v1(47.6,65.58) ; U4.3 v1(47.68,71.69) 47.71,71.72 C23.1
N11475055: length 7.5
  BOTTOM w0.762: Q4.3 46.93,79.95 R52.1 R51.1 51.46,79.95 51.84,80.33 Q5.3
N11475093: length 1.5
  BOTTOM w0.203: C26.1 50.82,64.47
  BOTTOM w0.381: 50.82,64.47 50.8,64.48 R30.2
N11475353: length 14.7
  TOP w0.762: J1.1 9.4,1.6 10.57,0.43 11.46,0.43
  BOTTOM w0.762: J1.1 9.4,1.65 10.54,0.51 11.46,0.51
N11475357: length 0.7
  BOTTOM w2.032: 9.86,15.39 J1.2
N11530054: length 5.3
  BOTTOM w0.508: 48.82,77.08 48.82,78.51 R52.2 ; 48.82,77.08 48.82,76.72 48.83,76.7 ; 48.82,77.08 Q4.1
  BOTTOM w0.762: VR3.1 48.83,76.7 R52.2
N11567485: length 2.2
  BOTTOM w1.27: 5.13,42.24 R1.2
N11567493: length 1.7
  BOTTOM w1.27: R2.1 10.9,42.72 10.89,42.72
N11571354: length 1.8
  BOTTOM w0.508: R15.1 49.35,54.57 D8.1
N11571367: length 1.9
  BOTTOM w0.508: D8.2 49.53,51.34 49.53,49.78 VR1.2
N11586649:
  vias: v2(2.44,66.01) v2(4.55,70.59) v2(4.52,68.33) v2(4.55,66.14) v2(4.65,72.49) v2(6.4,66.19)
N11591526: length 2.4
  BOTTOM w1.27: C35.2 R38.2
N12158428: length 38.1
  TOP w0.508: v1(26.98,22.36) 26.98,21.02 28.96,19.05 40.11,19.05 40.69,19.63 41.55,19.63 42.06,19.13 42.06,4.93 43.69,3.3 v1(43.71,3.3)
  BOTTOM w0.381: D9.1 42.72,2.31 v1(43.71,3.3) 43.71,3.43 Q7.4 ; U1.8 v1(26.98,22.36)
N12158455: length 2
  BOTTOM w0.762: D9.2 45.26,3.8 R40.1
N12185398: length 14.3
  BOTTOM w0.381: J2.B5 48.64,5.62 49.86,4.39 C16.2 50.54,4.24 D6.1
  BOTTOM w0.508: R43.1 53.12,11.71 52.12,10.7 52.12,9.02 53.16,7.98 53.16,4.75 52.65,4.24 D6.1
N12185402: length 14.9
  TOP w0.381: v1(47.14,12.57) 44.97,10.4 44.97,4.61 45.24,4.34 J2.A5
  BOTTOM w0.508: v1(47.14,12.57) 48.27,12.57 C37.2 48.36,12.6 D10.1 51.41,12.6 R37.2
N12185406: length 15.3
  TOP w0.508: v1(47.78,13.61) 51.16,10.24 v1(51.16,9.86)
  BOTTOM w0.305: v1(47.78,13.61) 48.9,14.73 48.9,19.95 48.59,20.26 U5.7
  BOTTOM w0.508: RT2.2 51.41,8.08 51.16,8.33 v1(51.16,9.86)
N12185524: length 9.4
  BOTTOM w0.305: C19.1 49.87,19.9 48.86,20.91 U5.6
  BOTTOM w0.508: C19.1 49.87,14.54 50.38,14.03 R37.1
N12185556: length 4.2
  TOP w0.203: 47.81,4.69 J2.B7
  TOP w0.305: J2.B6 47.79,5.34 J2.A7 J2.A6 47.79,4.84 J2.B7
  BOTTOM w0.508: J2.B6 J2.B7
N12185614: length 10.7
  BOTTOM w0.305: C20.1 49.17,21.56 U5.5
  BOTTOM w0.508: C20.1 52.04,19.43 52.55,18.92 52.55,14.61 R43.2
N12197697: length 6.6
  BOTTOM w0.381: R44.2 37.2,23.8 36.31,22.91 R21.1 35.61,22.91 34.67,23.85 34.03,23.85 C10.2 33.78,23.95 U1.1
N12203170: length 1.7
  BOTTOM w0.508: VR2.1 52.96,52.88 R17.2
N12231621: length 9
  BOTTOM w0.381: R47.2 54.09,69.06 54.11,69.09 R48.1 54.11,70.52 53.15,71.49 U2.2 50.8,72.54 50.8,74.98 D5.1
N12232589: length 3.6
  BOTTOM w0.381: R50.1 54.23,74.75 54.23,76.4 R49.2 54.23,76.48 54.23,77.88 Q5.1
N12263719: length 13.9
  BOTTOM w0.508: 42.86,26.64 43.84,26.64 45.06,27.86 48.62,27.86 49.61,26.87 49.61,26.09 D12.1 ; 42.86,26.64 Q9.2 ; 42.86,26.64 39.88,26.64 39.26,26.02 R13.1
N12263747: length 9
  BOTTOM w0.305: Q9.1 40.98,24.6 41.4,24.18 43.54,24.18 VR5.1
  BOTTOM w0.508: VR5.1 46.23,26.34 47.47,26.34 R11.2
N12279931: length 2.4
  BOTTOM w0.508: D11.1 52.11,25.08 53.1,24.09 R6.1
N122316481: length 2.3
  BOTTOM w0.381: R50.2 52.01,73.22 U2.1
N122329820: length 1.5
  BOTTOM w0.381: D5.2 50.53,77.48 R51.2

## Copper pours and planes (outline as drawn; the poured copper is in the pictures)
GND on TOP (solid shape): 22.3,0.05 20.52,0.05 19.68,0.33 20.52,0.61 19.68,0.89 20.52,1.17 19.68,1.45 20.52,1.73 22.3,1.73
GND on TOP (solid shape): 48.29,2.36 48.29,2.03 48.87,1.45 49.86,1.45 50.22,1.09 50.22,0.36 49.94,0.08 46.1,0.08 46.08,0.1 46.08,2.49 47.65,2.49 47.78,2.62 48.03,2.62
GND on TOP (solid shape): 50.14,9.73 50.14,8.69 49.48,8.03 48.31,8.03 48.23,7.95 48.23,7.77 48.13,7.67 47.8,7.67 47.78,7.7 46.05,7.7 46.02,7.72 46.02,9.53 46.71,10.21 49.66,10.21
GND on BOTTOM (solid shape): 50.34,10.26 50.34,8.56 50.22,8.43 47.9,8.43 47.78,8.56 47.78,10.29 47.93,10.44 50.16,10.44
GND on BOTTOM (solid shape): 48.21,2.31 48.21,2.24 48.41,2.03 49.35,2.03 49.61,2.29 54.41,2.29 54.84,1.85 54.84,0.61 54.42,0.19 50.05,0.19 50.04,0.18 47.9,0.18 47.6,0.48 47.6,2.31 47.83,2.54 47.98,2.54
GND on BOTTOM: 44.51,15.91 44.55,15.95 45.8,15.95 45.78,15.94 45.78,12.71 46.96,11.53 49.33,11.53 49.56,11.3 50.32,11.3 50.44,11.18 50.44,10.49 50.42,10.46 43.26,10.46 43.23,10.49 43.23,11.96 43.87,11.96 44.51,12.61
GND_SIGNAL on TOP: 26.54,9.65 35.84,9.65 36.77,10.58 38.09,10.58 38.1,10.59 39.83,10.59 40.39,10.03 40.39,9.35 37.59,6.55 27.41,6.55 26.34,7.62 26.34,9.4 26.31,9.42
GND_SIGNAL on BOTTOM: 27.46,6.55 26.11,7.9 26.11,9.12 26.29,9.3 26.31,9.3 26.34,9.27 27.58,9.27 28.02,9.7 30.63,9.7 30.94,10.01 30.94,11.35 30.96,11.38 33.83,11.38 33.86,11.35 33.86,9.93 34.3,9.49 36.26,9.49 36.65,9.88 36.65,11.3 36.7,11.35 39.62,11.35 40.39,12.12 41.07,12.12 42.29,13.34 42.29,15.93 42.32,15.95 43.66,15.95 43.69,15.93 43.69,13.23 42.57,12.12 42.57,10.72 42.32,10.46 42.06,10.46 42.04,10.44 40.67,10.44 40.16,9.93 40.16,9.17 37.54,6.55
GND_SIGNAL on BOTTOM: 25.58,19.46 31.42,19.46 31.98,20.02 31.98,22.23 31.95,22.25 31.98,22.28 34.59,22.28 34.59,21.29 36.08,19.8 36.54,19.8 36.86,19.48 32.72,19.48 31.45,18.21 25.63,18.21 25.55,18.29 25.55,19.43
VBUS_OUT on BOTTOM (solid shape): 22.3,0.05 20.52,0.05 19.68,0.33 20.52,0.61 19.68,0.89 20.52,1.17 19.68,1.45 20.52,1.73 22.3,1.73
VBUS_OUT on BOTTOM: 43.05,4.39 43.74,4.39 44.32,4.98 45.67,4.98 46.13,4.52 46.13,3.35 46.25,3.23 47.07,3.23 47.45,3.61 48.03,3.61 48.21,3.78 48.21,3.99 47.98,4.22 47.47,4.22 47.37,4.32 47.37,5.94 47.45,6.02 48.06,6.02 48.21,6.17 48.21,6.38 48.01,6.58 47.45,6.58 47.14,6.88 47.14,7.11 46.76,7.49 43.21,7.49 43.05,7.34
B+ on BOTTOM (solid shape): 26.42,61.37 26.42,57.3 26.16,57.05 24.26,57.05 24,57.3 24,61.37 24.26,61.62 26.16,61.62
B+ on BOTTOM (solid shape): 26.49,61.29 26.49,56.31 26.37,56.18 23.55,56.18 23.42,56.31 23.42,61.39 23.57,61.54 26.24,61.54
B+ on BOTTOM: 25.96,63.96 25.37,63.96 24.18,62.76 24.16,62.76 22.61,61.21 19.53,61.21 18.29,62.46 18.29,64.36 18.01,64.64 16,64.64 16,57.78 17.63,56.16 17.63,50.11 18.11,50.11 18.72,50.72 18.72,51 20.29,52.58 20.35,52.53 20.68,52.53 20.9,52.76 28.6,52.76 29.11,53.26 29.11,54.76 27.64,56.24 26.77,56.24 26.47,56.54 26.47,60.43 26.49,60.45 26.49,63.42
B+ on BOTTOM: 43.56,35.59 41.17,35.59 41.1,35.66 41.1,41.58 41.12,41.61 42.67,41.61 43.33,42.27 44.27,42.27 45.54,41 45.54,37.57
RTN on TOP: 6.1,81.05 11.84,81.05 15.09,77.8 21.77,77.8 22.56,77.01 22.56,74.52 21.49,73.46 19.51,73.46 18.16,74.8 10.46,74.8 9.46,75.81 6.82,75.81 6.1,76.53
RTN on TOP: 35.08,40.74 35.08,40.72 35.7,40.09 35.7,35.85 35.86,35.69 41.61,35.69 42.19,36.27 42.19,39.65 43.28,40.74 49.4,40.74 50.06,40.08 50.06,37.8 50.6,37.26 51.46,37.26 51.94,37.74 51.94,38.85 52.95,39.85 52.95,53.99 52.91,54.03 52.83,54.03 51.69,55.17 31.11,55.17 30.68,54.74 30.68,51.13 30.05,50.5 28.02,50.5 26.44,52.07 26.44,60.86 25.43,61.87 24.71,61.87 24.45,61.61 24.45,51.68 20.27,47.5 20.27,31.37 42.24,31.37 42.24,35.08 42.01,35.31 35.41,35.31 35.23,35.13 35.23,34.7 34.37,33.83 30.33,33.83 29.82,34.34 29.82,39.93 31.27,41.38 34.44,41.38
RTN on TOP: 42.21,36.27 42.21,34.67 42.04,34.49 35.53,34.49 34.54,33.5 30.02,33.5 29.49,34.04 29.49,37.57 29.62,37.57 31.5,35.69 34.42,35.69 35.69,36.96 36.14,36.96 36.6,36.5 36.6,36.32 42.16,36.32
RTN on BOTTOM: 5.97,81.08 10.46,81.08 10.9,80.64 10.9,76.68 10.34,76.12 9.83,76.12 9.73,76.02 5.92,76.02 5.92,81.03
RTN on BOTTOM: 26.14,38.23 26.14,39.6 25.07,40.67 20.68,40.67 20.27,41.07 20.27,48.49 22.33,50.55 30.23,50.55 30.84,51.16 40.46,51.16 40.47,51.17 41.38,50.26 41.38,44 40.21,42.82 37.03,42.82 35.74,41.53 31.42,41.53 29.79,39.9 29.79,39.83 29.82,39.8 29.82,35.94 25.32,35.94 25.25,36.02 25.25,37.69 25.3,37.74 25.65,37.74
RTN on BOTTOM: 17.4,78.71 24.56,78.71 29.11,74.17 30.99,74.17 31.83,73.33 31.83,72.92 30.91,72.01 29.26,72.01 25.93,68.68 25.93,66.09 25.35,65.51 24.71,65.51 22.48,63.27 21.64,63.27 21.08,63.83 21.08,64.8 23.57,67.28 23.57,71.83 21.92,73.48 17.42,73.48 17.4,73.51
VOUT on TOP: 27.1,5.82 37.77,5.82 41.1,9.14 41.2,9.14 41.3,9.04 41.3,8.64 41.33,8.61 41.33,2.16 40.59,1.42 27.18,1.42 20.45,8.15 20.45,9.37 21.27,10.2 22.8,10.2 23.38,9.61 24.42,9.61 25.7,8.33 25.7,7.21
VOUT on BOTTOM: 41.38,1.42 41.66,1.7 41.66,2.54 42.27,3.15 42.27,8.53 42.16,8.64 40.54,8.64 37.72,5.82 27.2,5.82 25.7,7.32 25.7,8.33 24.04,9.99 21.09,9.99 20.41,9.31 20.41,8.17 27.15,1.42
VRECT on TOP: 31.04,83.67 31.9,82.8 31.9,76.05 31.62,75.77 29.44,75.77 25.43,79.78 15.24,79.78 13.03,81.99 13.03,83.34 13.36,83.67
VRECT on BOTTOM: 12.4,73.56 12.27,73.69 12.27,81.56 11.43,82.4 4.34,82.4 3.35,81.41 3.35,76.23 3.15,76.02 0.76,76.02 0.76,82.85 1.52,83.62 32.64,83.62 33.58,82.68 33.58,82.22 33.21,81.85 32.5,81.85 31.9,81.25 31.9,76.1 31.62,75.82 29.49,75.82 25.45,79.86 16.1,79.86 14.78,78.54 14.78,73.76 14.58,73.56
N11472561 on BOTTOM: 39.29,41.38 39.29,35.56 39.27,35.53 37.72,35.53 37.24,36.02 34.59,36.02 34.59,37.49 37.77,40.67 37.77,41.33 37.82,41.38
N11473069 on BOTTOM: 24.56,14.15 26.19,14.15 26.7,13.64 28.07,13.64 28.07,11.3 27.84,11.07 26.11,11.07 26.11,12.37 25.83,12.65 24.56,12.65
N11473107 on BOTTOM: 33.55,35.99 31.95,35.99 31.95,38.81 32.41,39.27 33.38,39.27 33.55,39.09
N11473227 on TOP: 40.37,16.5 39.37,17.5 27.43,17.5 24.82,20.12 24.82,21.21 24.16,21.21 19.96,17.02 19.96,14.88 23.8,11.05 29.84,11.05 29.86,11.06 40.27,11.06 40.37,11.16
N11473227 on BOTTOM: 23.7,20.62 24.64,20.62 25.02,20.24 25.02,17.81 25.27,17.55 31.39,17.55 32.82,18.97 37.92,18.97 40.31,16.59 41.33,16.59 41.71,16.21 41.71,13.54 41,12.83 40.16,12.83 39.65,12.32 34.75,12.32 34.75,12.22 34.42,11.89 28.88,11.89 28.68,12.09 28.68,14.17 28.32,14.53 20.47,14.53 19.63,15.37 19.63,16.71 23.47,20.55 23.62,20.55
N11473427 on BOTTOM: 35.76,11.33 35.33,11.33 34.49,10.49 34.49,10.21 34.67,10.03 35.74,10.03 35.76,10.06
N11473427 on BOTTOM: 30.05,11.35 29.3,11.35 28.75,10.81 28.75,10.21 28.88,10.08 30.05,10.08
N11473829 on BOTTOM: 6.99,52.5 7.32,52.83 7.32,56.36 6.34,57.34 5.33,57.34 4.78,56.78 4.78,52.88 5.16,52.5 5.6,52.95 6.05,52.5 6.5,52.96 6.53,52.96
N11473955 on TOP: 19.91,70.56 19.91,66.88 19.08,66.04 15.47,66.04 14.33,64.9 14.33,56.31 13.03,55.02 11.3,55.02 10.79,55.52 10.79,56.97 11.76,57.94 11.76,59.82 10.06,61.52 10.06,64.41 12.06,66.42 12.06,72.01 13.16,73.1 17.37,73.1
N11473955 on BOTTOM: 12.37,70.71 19.74,70.71 19.91,70.54 19.91,65.71 19.79,65.58 14.88,65.58 14.17,64.87 14.17,56.44 12.8,55.07 11.46,55.07 10.77,55.75 10.77,56.9 11.77,57.9 11.77,59.75 10.21,61.32 10.21,64.52 10.24,64.52 12.24,66.52 12.24,70.59
N11473955 on BOTTOM: 13.03,52.5 13.36,52.83 13.36,56.64 10.85,56.64 10.79,56.59 10.79,52.91 11.2,52.5 11.65,52.95 12.09,52.5 12.55,52.96 12.57,52.96
N11474149 on TOP: 0.38,40.59 0.39,40.58 0.39,37.88 2.55,35.73 3.62,35.73 4.14,36.25 4.14,36.91 2.87,38.18 2.87,43 7.32,47.45 7.32,48.41 6.58,49.15 4.62,49.15 0.38,44.91
N11474149 on BOTTOM: 5.16,52.25 4.83,51.92 4.83,48.79 3.96,47.93 3.96,47.02 4.34,46.63 6.6,46.63 7.39,47.42 7.39,51.84 6.99,52.25 6.54,51.8 6.49,51.8 6.05,52.25 5.61,51.82 5.59,51.82
N11474157 on TOP: 15.38,38.95 12.09,35.66 11.1,35.66 10.62,36.14 10.62,37.29 12.73,39.4 12.73,45.35 10.69,47.38 10.69,48.36 11.57,49.24 13.3,49.24 15.38,47.16
N11474157 on BOTTOM: 13.39,46.86 13.39,51.89 13.03,52.25 12.57,51.79 12.55,51.79 12.09,52.25 11.66,51.82 11.63,51.82 11.2,52.25 10.82,51.87 10.82,47.22 11.4,46.63 13.16,46.63
N11474629 on BOTTOM (solid shape): 31.39,61.57 31.39,57.38 31.14,57.12 29.11,57.12 28.85,57.38 28.85,61.7 31.27,61.7
N11474629 on BOTTOM (solid shape): 34.62,67.26 34.62,64.06 34.42,63.86 31.67,63.86 31.47,64.06 31.47,67.31 31.65,67.49 34.39,67.49
N11474629 on BOTTOM (solid shape): 31.93,62.05 31.93,57.1 31.88,57.05 29.18,57.05 28.85,57.38 28.85,61.77 28.32,62.31 28.32,62.41 28.35,62.43 31.55,62.43
N11474629 on TOP: 42.41,81.9 43.54,80.77 43.54,59.99 42.52,58.98 28.83,58.98 28.32,59.49 28.32,68.43 30.44,70.55 32.83,70.55 33.66,71.37 33.66,81.9
N11474629 on BOTTOM: 33.65,80.64 42.65,80.64 42.79,80.51 42.79,59.27 35.43,59.27 34.8,58.64 34.8,57.3 34.54,57.05 28.93,57.05 28.88,57.1 28.88,61.75 28.32,62.31 28.32,68.4 30.44,70.52 33.44,70.52 35.47,72.56 35.47,73.75 34.71,74.51 34.67,74.51 33.65,75.53
N11474993 on BOTTOM: 46.79,74.63 49.45,74.63 50.16,73.91 50.16,72.21 50.95,71.42 50.95,70.84 51.23,70.56 53.06,70.56 53.09,70.54 53.09,65.79 53.75,65.13 53.75,62.05 52.63,60.93 50.22,60.93 50.22,61.54 50.57,61.9 50.57,63.32 52.37,63.32 52.5,63.45 52.5,65.15 51.92,65.74 50.7,65.74 50.52,65.91 50.52,67.49 51.1,68.07 51.1,68.99 50.52,69.57 50.52,70.64 50.14,71.02 49.1,71.02 48.95,71.17 48.95,72.34 48.77,72.52 47.57,72.52 47.29,72.24 45.14,72.24 45.09,72.29 45.09,72.62 45.14,72.67 46.84,72.67 46.86,72.64 47.09,72.64 47.4,72.95 47.4,73.41 46.76,74.04 46.76,74.6
N11475097 on BOTTOM: 1.42,27.79 1.96,27.25 3,27.25 5.16,29.41 8.05,29.41 8.59,29.95 8.59,31.04 7.53,32.09 3.85,32.09 3.81,32.13 2.9,32.13 1.42,30.66
N11475353 on TOP (solid shape): 13.18,1.45 12.34,1.17 13.18,0.89 12.34,0.61 13.18,0.33 12.34,0.05 10.57,0.05 10.57,1.73 12.34,1.73
N11475353 on BOTTOM (solid shape): 13.18,1.45 12.34,1.17 13.18,0.89 12.34,0.61 13.18,0.33 12.34,0.05 10.57,0.05 10.57,1.73 12.34,1.73
N11475353 on BOTTOM: 2.92,24.26 1.45,24.26 0.64,23.44 0.64,11.35 7.42,4.57 10.79,4.57 11.2,4.98 11.2,8.2 11.18,8.23 7.87,8.23 3.17,12.93 3.17,24
N11475357 on BOTTOM: 7.59,14.38 8.81,13.16 9.91,13.16 11.13,14.38 11.13,20.37 12.65,21.89 12.65,31.39 11.96,32.08 11.2,32.08 10.96,31.84 10.96,24.73 7.59,21.36
N11567485 on BOTTOM (solid shape): 6.43,42.39 5.92,42.39 5.92,39.19 6.43,39.19 6.43,38.58 4.24,38.58 4.24,43 6.43,43
N11567493 on BOTTOM (solid shape): 11.63,38.61 9.45,38.61 9.45,39.22 9.96,39.22 9.96,42.42 9.45,42.42 9.45,43.03 11.63,43.03
N11586649 on TOP: 8.56,73.2 10.06,71.7 10.06,66.95 8.69,65.58 1.17,65.58 0.69,66.07 0.69,73.13 0.76,73.2
N11586649 on BOTTOM: 8.48,73.2 0.81,73.2 0.71,73.1 0.71,66.07 1.22,65.56 8.69,65.56 10.03,66.9 10.03,71.65
N12265542 on BOTTOM: 22.73,14.15 21.01,14.15 20.55,13.69 20.55,10.54 20.62,10.46 22.15,10.46 22.17,10.49 22.17,11.81 22.15,11.84 22.15,12.01 22.73,12.6

Small or netless copper shapes (teardrops, artwork), in the pictures only: 2 on TOP

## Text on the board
Ref Des/Silkscreen Bottom: S/N
Ref Des/Silkscreen Top: L | 1912 | DER-805 | REV D
User.5: 11.  TRACE SPACE +/- 0.003" | 13. 2 LAYERS BOARD TOP,BOT. | PLEASE DELETE THESE PINS. | SLOTS
User.8: FIGURE | FINISHED_SIZE | 12.0 | 16.0 | 20.0 | 25.0 | 30.0 | 35.0 | 40.0 | 50.0 | 52.0 | 60.0 | 68.0 | 70.0 | 90.0 | 125.0 | 47.244x23.622 | DRILL CHART: TOP to BOTTOM | ALL UNITS ARE IN MILS | PLATED | NON-PLATED | QTY | 30 | 14 | 158 | 4 | 6 | 7 | 5 | 15 | 2 | 1
